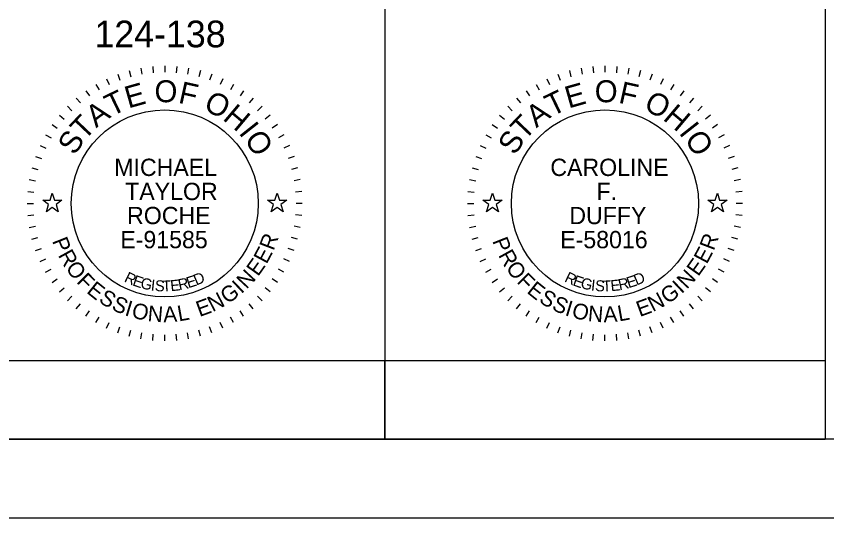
# Model space of a CAD drawing. Extents: x -21.9 to 47.3, y 14.1 to 48.7.
# Drawn here: x 24.06 to 29.21, y 26.73 to 29.92 of the extents above; entities that cross this region are included whole.
import ezdxf

# ---------------------------------------------------------------- set-up
doc = ezdxf.new("R2010")
doc.units = 0
for name, color, linetype in [('SH_Border', 7, 'Continuous'), ('SH_Cut_Line', 7, 'Continuous'), ('SH_Data', 7, 'Continuous'), ('SH_Seal', 7, 'Continuous'), ('SH_Text', 7, 'Continuous')]:
    doc.layers.add(name, color=color, linetype=linetype)

msp = doc.modelspace()

# ---------------------------------------------------------------- linework, layer by layer
at = {"layer": 'SH_Border'}
msp.add_lwpolyline([(1.5, 48.2334), (33.5, 48.2334), (33.5, 27.2334), (1.5, 27.2334)], close=True, dxfattribs=at)
at = {"layer": 'SH_Cut_Line'}
msp.add_lwpolyline([(0, 26.7334), (34, 26.7334), (34, 48.7334), (0, 48.7334)], close=True, dxfattribs=at)
at = {"layer": 'SH_Data'}
for p, q in [((26.4, 30.7334), (26.4, 27.2334)), ((29.2, 30.7334), (29.2, 27.2334)), ((23.6, 27.2334), (26.4, 27.2334)), ((26.4, 27.2334), (29.2, 27.2334))]:
    msp.add_line(p, q, dxfattribs=at)
for points in [[(23.6, 27.2334), (23.6, 27.7334), (26.4, 27.7334), (26.4, 27.2334)], [(26.4, 27.2334), (26.4, 27.7334), (29.2, 27.7334), (29.2, 27.2334)]]:
    msp.add_lwpolyline(points, close=True, dxfattribs=at)
at = {"layer": 'SH_Seal'}
for p, q in [((24.8481, 29.5951), (24.855, 29.5557)), ((24.9237, 29.6051), (24.9272, 29.5652)), ((25, 29.6084), (25, 29.5684)), ((25.0763, 29.6051), (25.0728, 29.5652)), ((25.1519, 29.5951), (25.145, 29.5557)), ((27.6481, 29.5951), (27.655, 29.5557)), ((27.7237, 29.6051), (27.7272, 29.5652)), ((27.8, 29.6084), (27.8, 29.5684)), ((27.8763, 29.6051), (27.8728, 29.5652)), ((27.9519, 29.5951), (27.945, 29.5557)), ((24.7007, 29.5556), (24.7144, 29.5181)), ((24.7735, 29.5786), (24.7839, 29.54)), ((25.2265, 29.5786), (25.2161, 29.54)), ((25.2993, 29.5556), (25.2856, 29.5181)), ((27.5007, 29.5556), (27.5144, 29.5181)), ((27.5735, 29.5786), (27.5839, 29.54)), ((28.0265, 29.5786), (28.0161, 29.54)), ((28.0993, 29.5556), (28.0856, 29.5181)), ((24.5625, 29.4912), (24.5825, 29.4565)), ((24.6302, 29.5264), (24.6471, 29.4902)), ((25.3698, 29.5264), (25.3529, 29.4902)), ((25.4375, 29.4912), (25.4175, 29.4565)), ((27.3625, 29.4912), (27.3825, 29.4565)), ((27.4302, 29.5264), (27.4471, 29.4902)), ((28.1698, 29.5264), (28.1529, 29.4902)), ((28.2375, 29.4912), (28.2175, 29.4565)), ((24.4981, 29.4502), (24.5211, 29.4174)), ((25.5019, 29.4502), (25.4789, 29.4174)), ((27.2981, 29.4502), (27.3211, 29.4174)), ((28.3019, 29.4502), (28.2789, 29.4174)), ((24.4376, 29.4037), (24.4633, 29.3731)), ((25.5624, 29.4037), (25.5367, 29.3731)), ((27.2376, 29.4037), (27.2633, 29.3731)), ((28.3624, 29.4037), (28.3367, 29.3731)), ((24.3813, 29.3521), (24.4096, 29.3238)), ((25.6187, 29.3521), (25.5904, 29.3238)), ((27.1813, 29.3521), (27.2096, 29.3238)), ((28.4187, 29.3521), (28.3904, 29.3238)), ((24.3297, 29.2959), (24.3604, 29.2701)), ((25.6703, 29.2959), (25.6396, 29.2701)), ((27.1297, 29.2959), (27.1604, 29.2701)), ((28.4703, 29.2959), (28.4396, 29.2701)), ((24.2832, 29.2353), (24.316, 29.2123)), ((25.7168, 29.2353), (25.684, 29.2123)), ((27.0832, 29.2353), (27.116, 29.2123)), ((28.5168, 29.2353), (28.484, 29.2123)), ((24.2422, 29.1709), (24.2769, 29.1509)), ((25.7578, 29.1709), (25.7231, 29.1509)), ((27.0422, 29.1709), (27.0769, 29.1509)), ((28.5578, 29.1709), (28.5231, 29.1509)), ((24.207, 29.1032), (24.2432, 29.0863)), ((25.793, 29.1032), (25.7568, 29.0863)), ((27.007, 29.1032), (27.0432, 29.0863)), ((28.593, 29.1032), (28.5568, 29.0863)), ((24.1778, 29.0327), (24.2154, 29.019)), ((25.8222, 29.0327), (25.7846, 29.019)), ((26.9778, 29.0327), (27.0154, 29.019)), ((28.6222, 29.0327), (28.5846, 29.019)), ((24.1548, 28.9599), (24.1935, 28.9495)), ((25.8452, 28.9599), (25.8065, 28.9495)), ((26.9548, 28.9599), (26.9935, 28.9495)), ((28.6452, 28.9599), (28.6065, 28.9495)), ((24.1383, 28.8854), (24.1777, 28.8784)), ((25.8617, 28.8854), (25.8223, 28.8784)), ((26.9383, 28.8854), (26.9777, 28.8784)), ((28.6617, 28.8854), (28.6223, 28.8784)), ((24.1283, 28.8097), (24.1682, 28.8062)), ((25.8717, 28.8097), (25.8318, 28.8062)), ((26.9283, 28.8097), (26.9682, 28.8062)), ((28.6717, 28.8097), (28.6318, 28.8062)), ((24.125, 28.7334), (24.165, 28.7334)), ((25.875, 28.7334), (25.835, 28.7334)), ((26.925, 28.7334), (26.965, 28.7334)), ((28.675, 28.7334), (28.635, 28.7334)), ((24.1283, 28.6571), (24.1682, 28.6606)), ((25.8717, 28.6571), (25.8318, 28.6606)), ((26.9283, 28.6571), (26.9682, 28.6606)), ((28.6717, 28.6571), (28.6318, 28.6606)), ((24.1383, 28.5815), (24.1777, 28.5884)), ((25.8617, 28.5815), (25.8223, 28.5884)), ((26.9383, 28.5815), (26.9777, 28.5884)), ((28.6617, 28.5815), (28.6223, 28.5884)), ((24.1548, 28.5069), (24.1935, 28.5173)), ((25.8452, 28.5069), (25.8065, 28.5173)), ((26.9548, 28.5069), (26.9935, 28.5173)), ((28.6452, 28.5069), (28.6065, 28.5173)), ((24.1778, 28.4341), (24.2154, 28.4478)), ((25.8222, 28.4341), (25.7846, 28.4478)), ((26.9778, 28.4341), (27.0154, 28.4478)), ((28.6222, 28.4341), (28.5846, 28.4478)), ((24.207, 28.3636), (24.2432, 28.3805)), ((25.793, 28.3636), (25.7568, 28.3805)), ((27.007, 28.3636), (27.0432, 28.3805)), ((28.593, 28.3636), (28.5568, 28.3805)), ((24.2422, 28.2959), (24.2769, 28.3159)), ((25.7578, 28.2959), (25.7231, 28.3159)), ((27.0422, 28.2959), (27.0769, 28.3159)), ((28.5578, 28.2959), (28.5231, 28.3159)), ((24.2832, 28.2315), (24.316, 28.2545)), ((25.7168, 28.2315), (25.684, 28.2545)), ((27.0832, 28.2315), (27.116, 28.2545)), ((28.5168, 28.2315), (28.484, 28.2545)), ((24.3297, 28.171), (24.3604, 28.1967)), ((25.6703, 28.171), (25.6396, 28.1967)), ((27.1297, 28.171), (27.1604, 28.1967)), ((28.4703, 28.171), (28.4396, 28.1967)), ((24.3813, 28.1147), (24.4096, 28.143)), ((25.6187, 28.1147), (25.5904, 28.143)), ((27.1813, 28.1147), (27.2096, 28.143)), ((28.4187, 28.1147), (28.3904, 28.143)), ((24.4376, 28.0631), (24.4633, 28.0938)), ((24.4981, 28.0167), (24.5211, 28.0494)), ((25.5019, 28.0167), (25.4789, 28.0494)), ((25.5624, 28.0631), (25.5367, 28.0938)), ((27.2376, 28.0631), (27.2633, 28.0938)), ((27.2981, 28.0167), (27.3211, 28.0494)), ((28.3019, 28.0167), (28.2789, 28.0494)), ((28.3624, 28.0631), (28.3367, 28.0938)), ((24.5625, 27.9756), (24.5825, 28.0103)), ((25.4375, 27.9756), (25.4175, 28.0103)), ((27.3625, 27.9756), (27.3825, 28.0103)), ((28.2375, 27.9756), (28.2175, 28.0103)), ((24.6302, 27.9404), (24.6471, 27.9766)), ((24.7007, 27.9112), (24.7144, 27.9488)), ((25.2993, 27.9112), (25.2856, 27.9488)), ((25.3698, 27.9404), (25.3529, 27.9766)), ((27.4302, 27.9404), (27.4471, 27.9766)), ((27.5007, 27.9112), (27.5144, 27.9488)), ((28.0993, 27.9112), (28.0856, 27.9488)), ((28.1698, 27.9404), (28.1529, 27.9766)), ((24.7735, 27.8882), (24.7839, 27.9269)), ((24.8481, 27.8717), (24.855, 27.9111)), ((24.9237, 27.8617), (24.9272, 27.9016)), ((25, 27.8584), (25, 27.8984)), ((25.0763, 27.8617), (25.0728, 27.9016)), ((25.1519, 27.8717), (25.145, 27.9111)), ((25.2265, 27.8882), (25.2161, 27.9269)), ((27.5735, 27.8882), (27.5839, 27.9269)), ((27.6481, 27.8717), (27.655, 27.9111)), ((27.7237, 27.8617), (27.7272, 27.9016)), ((27.8, 27.8584), (27.8, 27.8984)), ((27.8763, 27.8617), (27.8728, 27.9016)), ((27.9519, 27.8717), (27.945, 27.9111)), ((28.0265, 27.8882), (28.0161, 27.9269))]:
    msp.add_line(p, q, dxfattribs=at)
for points in [[(24.2236, 28.7534), (24.2705, 28.7534), (24.285, 28.7979), (24.2995, 28.7534), (24.3464, 28.7534), (24.3085, 28.7258), (24.323, 28.6812), (24.285, 28.7088), (24.247, 28.6812), (24.2615, 28.7258)], [(25.6536, 28.7534), (25.7005, 28.7534), (25.715, 28.7979), (25.7295, 28.7534), (25.7764, 28.7534), (25.7385, 28.7258), (25.753, 28.6812), (25.715, 28.7088), (25.677, 28.6812), (25.6915, 28.7258)], [(27.0236, 28.7534), (27.0705, 28.7534), (27.085, 28.7979), (27.0995, 28.7534), (27.1464, 28.7534), (27.1085, 28.7258), (27.123, 28.6812), (27.085, 28.7088), (27.047, 28.6812), (27.0615, 28.7258)], [(28.4536, 28.7534), (28.5005, 28.7534), (28.515, 28.7979), (28.5295, 28.7534), (28.5764, 28.7534), (28.5385, 28.7258), (28.553, 28.6812), (28.515, 28.7088), (28.477, 28.6812), (28.4915, 28.7258)]]:
    msp.add_lwpolyline(points, close=True, dxfattribs=at)
for centre in [(25, 28.7334), (27.8, 28.7334)]:
    msp.add_circle(centre, 0.595, dxfattribs=at)

# ---------------------------------------------------------------- texts
for s, height, rotation, p in [('E', 0.14, 15.7571, (24.7684, 29.3372)), ('O', 0.14, 359.7812, (24.9347, 29.3777)), ('F', 0.14, 347.4362, (25.0811, 29.3751)), ('E', 0.14, 15.7571, (27.5684, 29.3372)), ('O', 0.14, 359.7812, (27.7347, 29.3777)), ('F', 0.14, 347.4362, (27.8811, 29.3751)), ('T', 0.14, 25.7167, (24.6616, 29.2852)), ('O', 0.14, 332.2586, (25.2398, 29.3349)), ('T', 0.14, 25.7167, (27.4616, 29.2852)), ('O', 0.14, 332.2586, (28.0398, 29.3349)), ('A', 0.14, 36.4747, (24.5634, 29.2115)), ('H', 0.14, 319.9136, (25.3632, 29.2695)), ('A', 0.14, 36.4747, (27.3634, 29.2115)), ('H', 0.14, 319.9136, (28.1632, 29.2695)), ('T', 0.14, 46.4344, (24.4883, 29.1299)), ('T', 0.14, 46.4344, (27.2883, 29.1299)), ('I', 0.14, 308.367, (25.4665, 29.1817)), ('I', 0.14, 308.367, (28.2665, 29.1817)), ('S', 0.14, 57.1924, (24.4281, 29.0348)), ('O', 0.14, 303.1491, (25.5021, 29.1423)), ('S', 0.14, 57.1924, (27.2281, 29.0348)), ('O', 0.14, 303.1491, (28.3021, 29.1423)), ('P', 0.1, 291.494, (24.2823, 28.4955)), ('R', 0.1, 69.2322, (25.6919, 28.4288)), ('P', 0.1, 291.494, (27.0823, 28.4955)), ('R', 0.1, 69.2322, (28.4919, 28.4288)), ('E', 0.1, 61.9951, (25.6476, 28.3433)), ('E', 0.1, 61.9951, (28.4476, 28.3433)), ('R', 0.1, 298.7311, (24.319, 28.4051)), ('R', 0.1, 298.7311, (27.119, 28.4051)), ('O', 0.1, 306.4666, (24.3655, 28.3217)), ('E', 0.1, 54.758, (25.5933, 28.2648)), ('O', 0.1, 306.4666, (27.1655, 28.3217)), ('E', 0.1, 54.758, (28.3933, 28.2648)), ('N', 0.1, 47.0224, (25.5202, 28.1842)), ('N', 0.1, 47.0224, (28.3202, 28.1842)), ('F', 0.1, 314.7068, (24.4343, 28.2317)), ('R', 0.07, 334.487, (24.7375, 28.2385)), ('E', 0.07, 341.04, (24.7906, 28.2135)), ('G', 0.07, 347.4752, (24.8414, 28.1952)), ('R', 0.07, 11.9184, (25.0925, 28.1808)), ('E', 0.07, 17.6836, (25.1498, 28.1936)), ('D', 0.07, 23.3052, (25.201, 28.2104)), ('F', 0.1, 314.7068, (27.2343, 28.2317)), ('R', 0.07, 334.487, (27.5375, 28.2385)), ('E', 0.07, 341.04, (27.5906, 28.2135)), ('G', 0.07, 347.4752, (27.6414, 28.1952)), ('R', 0.07, 11.9184, (27.8925, 28.1808)), ('E', 0.07, 17.6836, (27.9498, 28.1936)), ('D', 0.07, 23.3052, (28.001, 28.2104)), ('E', 0.1, 321.4393, (24.4978, 28.1682)), ('I', 0.07, 353.7858, (24.9091, 28.1802)), ('S', 0.07, 356.8926, (24.9358, 28.1763)), ('T', 0.07, 3.0061, (24.9857, 28.1721)), ('E', 0.07, 6.0117, (25.0389, 28.1746)), ('G', 0.1, 35.0469, (25.3981, 28.0904)), ('I', 0.1, 43.287, (25.4868, 28.1548)), ('E', 0.1, 321.4393, (27.2978, 28.1682)), ('I', 0.07, 353.7858, (27.7091, 28.1802)), ('S', 0.07, 356.8926, (27.7358, 28.1763)), ('T', 0.07, 3.0061, (27.7857, 28.1721)), ('E', 0.07, 6.0117, (27.8389, 28.1746)), ('G', 0.1, 35.0469, (28.1981, 28.0904)), ('I', 0.1, 43.287, (28.2868, 28.1548)), ('S', 0.1, 328.6764, (24.5743, 28.1086)), ('N', 0.1, 27.3113, (25.3045, 28.0409)), ('S', 0.1, 328.6764, (27.3743, 28.1086)), ('N', 0.1, 27.3113, (28.1045, 28.0409)), ('S', 0.1, 335.9134, (24.6564, 28.06)), ('I', 0.1, 343.1505, (24.7406, 28.0231)), ('O', 0.1, 346.8859, (24.7839, 28.0085)), ('E', 0.1, 20.0742, (25.2212, 28.0104)), ('S', 0.1, 335.9134, (27.4564, 28.06)), ('I', 0.1, 343.1505, (27.5406, 28.0231)), ('O', 0.1, 346.8859, (27.5839, 28.0085)), ('E', 0.1, 20.0742, (28.0212, 28.0104)), ('N', 0.1, 355.1261, (24.8888, 27.9852)), ('A', 0.1, 2.8617, (24.9923, 27.9771)), ('L', 0.1, 10.0987, (25.0894, 27.9825)), ('N', 0.1, 355.1261, (27.6888, 27.9852)), ('A', 0.1, 2.8617, (27.7923, 27.9771)), ('L', 0.1, 10.0987, (27.8894, 27.9825))]:
    msp.add_text(s, height=height, rotation=rotation, dxfattribs=at).set_placement(p)
for s, p in [('MICHAEL', (24.6789, 28.9083)), ('CAROLINE', (27.4526, 28.9083)), ('TAYLOR', (24.7481, 28.755)), ('F.', (27.7459, 28.755)), ('ROCHE', (24.7606, 28.6018)), ('DUFFY', (27.5735, 28.6018)), ('E-91585', (24.7173, 28.4485)), ('E-58016', (27.5154, 28.4485))]:
    msp.add_text(s, height=0.11, dxfattribs=at).set_placement(p)
at = {"layer": 'SH_Text'}
msp.add_text('124-138', height=0.17, dxfattribs=at).set_placement((24.553, 29.7269))

doc.saveas('drawing.dxf')
